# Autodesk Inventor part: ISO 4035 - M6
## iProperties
Author: Philippe
Created: 2001-12
Part Number: ISO 4035 - M6
Material: Par défaut
Catalog Web Link: file:///C:/Program Files/Autodesk/Inventor 5/Content/Iso/index.htm?doNavigateId=83012FF0-6BA1-417C-899B-D5B285169CF3|D3FB09DD3FC14D7E95503048018C615B|true
Description: Ecrou hexagonal
Document SubType Name: Standard Catalog Part
Standard: ISO 4035 - M6
Designer: Philippe
CLASSIFICATION: 31161727 un/spsc
MANUFACTURER: ISO Système de normes
Control State: 0
Master: False
Checked Out: False
PropertySet Name: Design Tracking Control
Shininess: 20.0
Angle Display Precision: 2
Document Length Units: 11269
Document Angle Units: 11283
Document Time Units: 11279
Document Mass Units: 11290
Document Length Units Precision: 3
Document Angle Units Precision: 2
Compacted: False
PropertySet Name: _Private Model Information
Density: 0.0
Volumn: 0.0
Area: 0.0
PropertySet Name: Model Information
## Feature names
1. Base1
